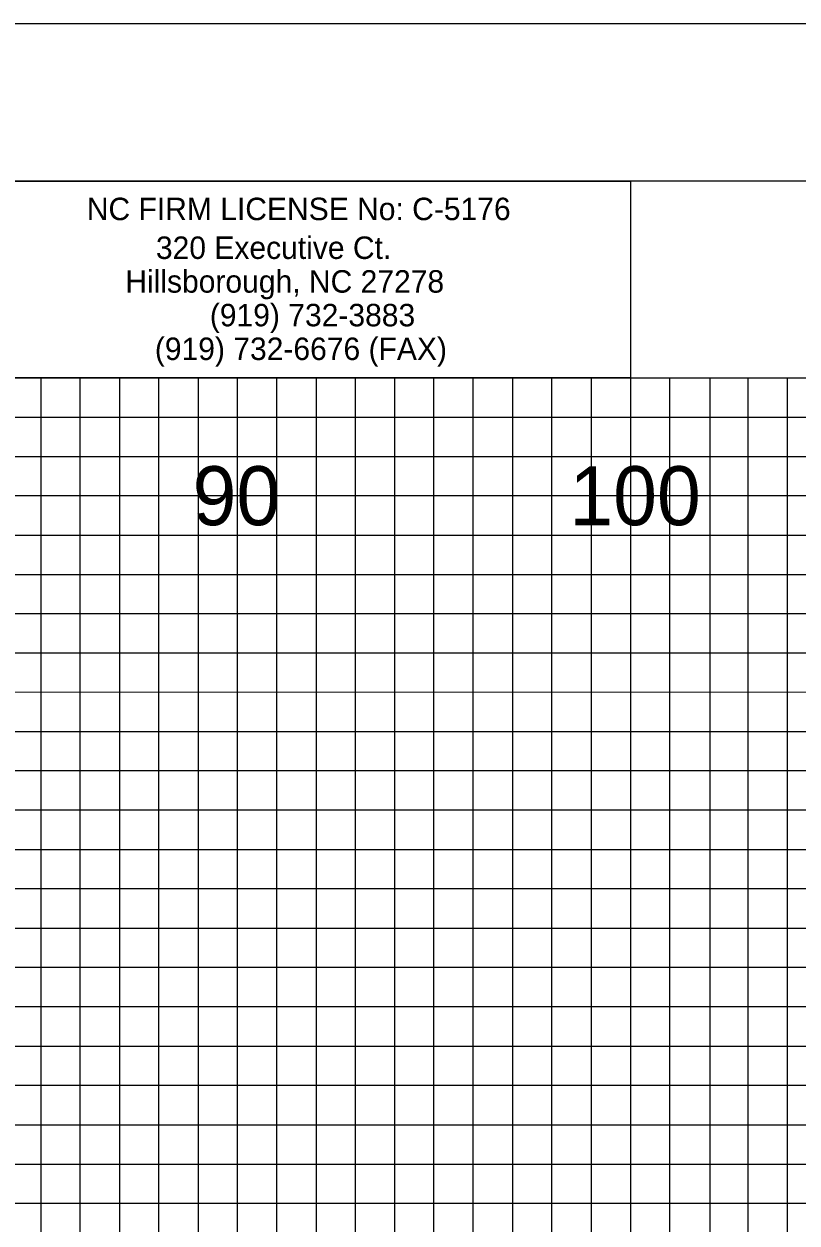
# Model space of a CAD drawing. Extents: x -13 to 323, y 655 to 874.
# Drawn here: x 244.57 to 264.24, y 843.5 to 874 of the extents above; entities that cross this region are included whole.
import ezdxf

# ---------------------------------------------------------------- set-up
doc = ezdxf.new("R2010")
doc.units = 0
for name, color, linetype in [('Exist Cross Section Cell', 7, 'Continuous'), ('Prop CMT Guardrail Widen Shoulder', 7, 'Continuous'), ('Prop CMT Pvmt Course 3', 7, 'Continuous'), ('Prop CMT Shld Paved Course 1', 7, 'Continuous'), ('Prop CMT Shld Paved Course 2', 7, 'Continuous'), ('Prop CMT Shld Paved Course 3', 7, 'Continuous'), ('Prop CMT Slope Grass', 7, 'Continuous'), ('Prop CMT Subgrade Earthwork', 7, 'Continuous'), ('Prop XS Earthwork Shape', 7, 'Continuous'), ('Scratch_Level_3', 7, 'Continuous')]:
    doc.layers.add(name, color=color, linetype=linetype)

msp = doc.modelspace()

# ---------------------------------------------------------------- linework, layer by layer
at = {"layer": 'Prop CMT Pvmt Course 3'}
msp.add_lwpolyline([(-13.4, 655), (323.3, 655), (323.3, 874), (-13.4, 874)], close=True, dxfattribs=at)
at = {"layer": 'Prop CMT Shld Paved Course 1'}
for p, q in [((260, 869), (260, 867.98)), ((260, 867), (260, 865.89)), ((0, 864), (320, 864))]:
    msp.add_line(p, q, dxfattribs=at)
for points in [[(0, 863), (270, 863), (320, 863)], [(320, 862), (0, 862)], [(0, 861), (320, 861)], [(320, 859), (0, 859)], [(0, 858), (320, 858)], [(320, 857), (0, 856.98)], [(0, 856), (320, 856)], [(320, 854), (0, 854)], [(0, 853), (320, 853), (320, 852), (0, 852)], [(0, 851), (320, 851), (320, 849), (0, 849)], [(0, 848), (320, 848), (320, 847), (0, 847)], [(0, 846), (320, 846), (320, 844), (0, 844)]]:
    msp.add_lwpolyline(points, dxfattribs=at)
at = {"layer": 'Prop CMT Shld Paved Course 2'}
for points in [[(320, 870), (0, 870), (0, 660), (320, 660)], [(280, 870), (260, 870), (260, 865), (280, 865)]]:
    msp.add_lwpolyline(points, close=True, dxfattribs=at)
at = {"layer": 'Prop CMT Shld Paved Course 3'}
for points in [[(246, 870), (247, 870)], [(248, 870), (249, 870)], [(251, 870), (252, 870)], [(253, 870), (254, 870)], [(256, 870), (257, 870)], [(258, 870), (259, 870)], [(245, 660), (246, 660), (246, 865)], [(247, 865), (247, 660)], [(247, 660), (248, 660), (248, 865)], [(249, 865), (249, 660)], [(250, 660), (251, 660), (251, 865)], [(252, 865), (252, 660)], [(252, 660), (253, 660), (253, 865)], [(254, 865), (254, 660)], [(255, 660), (256, 660), (256, 865)], [(257, 865), (257, 660)], [(257, 660), (258, 660), (258, 865)], [(259, 865), (259, 660)], [(260, 660), (261, 660), (261, 865), (262.02, 865), (262.02, 660)], [(262, 660), (263, 660), (263, 865), (263.99, 865), (263.99, 660)]]:
    msp.add_lwpolyline(points, dxfattribs=at)
at = {"layer": 'Prop CMT Slope Grass'}
for points in [[(235, 870), (245, 870)], [(255, 870), (259.93, 870), (260, 870), (260, 865), (264.99, 865), (264.99, 660), (275, 660), (275, 865), (280, 865)], [(0, 865), (275, 865)], [(0, 845), (320, 845), (320, 865)], [(245, 865), (245, 660), (255, 660), (255, 865)], [(320, 855), (0, 855)]]:
    msp.add_lwpolyline(points, dxfattribs=at)
at = {"layer": 'Prop CMT Subgrade Earthwork'}
msp.add_lwpolyline([(-10.8, 659), (322.4, 659), (322.4, 870), (-10.8, 870)], close=True, dxfattribs=at)
at = {"layer": 'Prop XS Earthwork Shape'}
msp.add_lwpolyline([(221.902, 870), (260, 870), (260, 865), (221.902, 865)], close=True, dxfattribs=at)
at = {"layer": 'Scratch_Level_3'}
for p, q in [((250, 870), (240, 870)), ((260, 870), (260, 660)), ((250, 660), (250, 865))]:
    msp.add_line(p, q, dxfattribs=at)
for points in [[(320, 865), (320, 850), (0, 850)], [(0, 860), (320, 860)]]:
    msp.add_lwpolyline(points, dxfattribs=at)

# ---------------------------------------------------------------- texts
at = {"layer": 'Exist Cross Section Cell'}
for s, p in [('90', (248.858, 861.25)), ('100', (258.444, 861.25))]:
    msp.add_text(s, height=1.5, dxfattribs=at).set_placement(p)
at = {"layer": 'Prop CMT Guardrail Widen Shoulder'}
msp.add_text('NC FIRM LICENSE No: C-5176', height=0.57146, dxfattribs=at).set_placement((246.166, 869.01))
for s, p in [('320 Executive Ct.', (247.925, 868.023)), ('Hillsborough, NC 27278', (247.146, 867.166)), ('(919) 732-3883', (249.297, 866.309)), ('(919) 732-6676 (FAX)', (247.898, 865.452))]:
    msp.add_text(s, height=0.57146, rotation=360, dxfattribs=at).set_placement(p)

doc.saveas('drawing.dxf')
